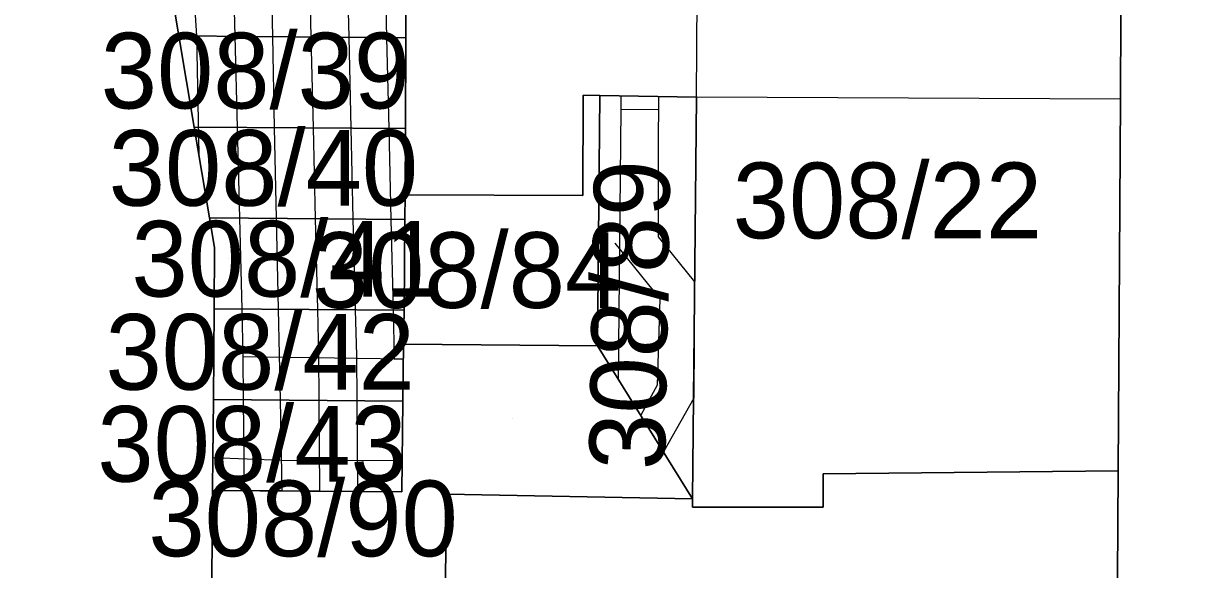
# Model space of a CAD drawing. Extents: x -263423 to -261326, y -1240067 to -1237864.
# Drawn here: x -263138.22 to -263106.91, y -1239151.4 to -1239136.99 of the extents above; entities that cross this region are included whole.
import ezdxf

# ---------------------------------------------------------------- set-up
doc = ezdxf.new("R2010")
doc.units = 0
for name, color, linetype in [('body_kn', 7, 'Continuous'), ('kladpar_druhypozemkov', 7, 'Continuous'), ('kladpar_hranice', 7, 'Continuous'), ('kladpar_parcelnecisla', 7, 'Continuous'), ('kladpar_plochy', 7, 'Continuous'), ('tarchy_linie', 7, 'Continuous'), ('zappar_hrandruhpozemk', 7, 'Continuous')]:
    doc.layers.add(name, color=color, linetype=linetype)

msp = doc.modelspace()

# ---------------------------------------------------------------- linework, layer by layer
at = {"layer": 'body_kn'}
for p, q in [((-263134.12, -1239137.31), (-263134.12, -1239137.31)), ((-263134.12, -1239137.31), (-263134.12, -1239137.31)), ((-263133.65, -1239137.31), (-263133.65, -1239137.31)), ((-263132.64, -1239137.32), (-263132.64, -1239137.32)), ((-263131.65, -1239137.33), (-263131.65, -1239137.33)), ((-263130.63, -1239137.34), (-263130.63, -1239137.34)), ((-263129.63, -1239137.35), (-263129.63, -1239137.35)), ((-263128.63, -1239137.36), (-263128.63, -1239137.36)), ((-263128.12, -1239137.36), (-263128.12, -1239137.36)), ((-263123.43, -1239138.88), (-263123.43, -1239138.88)), ((-263122.99, -1239138.89), (-263122.99, -1239138.89)), ((-263122.99, -1239138.89), (-263122.99, -1239138.89)), ((-263122.44, -1239138.9), (-263122.44, -1239138.9)), ((-263122.44, -1239138.9), (-263122.44, -1239138.9)), ((-263121.44, -1239138.91), (-263121.44, -1239138.91)), ((-263121.44, -1239138.91), (-263121.44, -1239138.91)), ((-263120.44, -1239138.93), (-263120.44, -1239138.93)), ((-263120.44, -1239138.93), (-263120.44, -1239138.93)), ((-263109.23, -1239138.98), (-263109.23, -1239138.98)), ((-263109.23, -1239138.98), (-263109.23, -1239138.98)), ((-263122.44, -1239139.25), (-263122.44, -1239139.25)), ((-263122.44, -1239139.25), (-263122.44, -1239139.25)), ((-263121.46, -1239139.26), (-263121.46, -1239139.26)), ((-263133.72, -1239139.72), (-263133.72, -1239139.72)), ((-263133.72, -1239139.72), (-263133.72, -1239139.72)), ((-263132.58, -1239139.73), (-263132.58, -1239139.73)), ((-263131.6, -1239139.74), (-263131.6, -1239139.74)), ((-263130.57, -1239139.74), (-263130.57, -1239139.74)), ((-263129.58, -1239139.75), (-263129.58, -1239139.75)), ((-263128.57, -1239139.76), (-263128.57, -1239139.76)), ((-263128.13, -1239139.76), (-263128.13, -1239139.76)), ((-263121.45, -1239140.26), (-263121.45, -1239140.26)), ((-263133.59, -1239140.45), (-263133.59, -1239140.45)), ((-263128.14, -1239141.51), (-263128.14, -1239141.51)), ((-263128.14, -1239141.51), (-263128.14, -1239141.51)), ((-263123.44, -1239141.53), (-263123.44, -1239141.53)), ((-263133.31, -1239142.12), (-263133.31, -1239142.12)), ((-263133.31, -1239142.12), (-263133.31, -1239142.12)), ((-263132.52, -1239142.13), (-263132.52, -1239142.13)), ((-263131.55, -1239142.13), (-263131.55, -1239142.13)), ((-263130.52, -1239142.14), (-263130.52, -1239142.14)), ((-263129.52, -1239142.15), (-263129.52, -1239142.15)), ((-263128.52, -1239142.16), (-263128.52, -1239142.16)), ((-263128.15, -1239142.16), (-263128.15, -1239142.16)), ((-263133.18, -1239142.9), (-263133.18, -1239142.9)), ((-263122.6, -1239142.79), (-263122.6, -1239142.79)), ((-263121.45, -1239142.62), (-263121.45, -1239142.62)), ((-263120.49, -1239143.81), (-263120.49, -1239143.81)), ((-263121.41, -1239144.26), (-263121.41, -1239144.26)), ((-263133.19, -1239144.52), (-263133.19, -1239144.52)), ((-263133.19, -1239144.52), (-263133.19, -1239144.52)), ((-263132.46, -1239144.53), (-263132.46, -1239144.53)), ((-263131.5, -1239144.53), (-263131.5, -1239144.53)), ((-263130.46, -1239144.54), (-263130.46, -1239144.54)), ((-263129.46, -1239144.55), (-263129.46, -1239144.55)), ((-263128.46, -1239144.56), (-263128.46, -1239144.56)), ((-263128.17, -1239144.56), (-263128.17, -1239144.56)), ((-263128.18, -1239145.46), (-263128.18, -1239145.46)), ((-263128.18, -1239145.46), (-263128.18, -1239145.46)), ((-263123.05, -1239145.5), (-263123.05, -1239145.5)), ((-263132.43, -1239145.78), (-263132.43, -1239145.78)), ((-263132.43, -1239145.78), (-263132.43, -1239145.78)), ((-263130.43, -1239145.76), (-263130.43, -1239145.76)), ((-263129.43, -1239145.76), (-263129.43, -1239145.76)), ((-263128.43, -1239145.84), (-263128.43, -1239145.84)), ((-263128.19, -1239145.84), (-263128.19, -1239145.84)), ((-263122.51, -1239146.37), (-263122.51, -1239146.37)), ((-263121.48, -1239146.54), (-263121.48, -1239146.54)), ((-263133.21, -1239146.92), (-263133.21, -1239146.92)), ((-263133.21, -1239146.92), (-263133.21, -1239146.92)), ((-263132.42, -1239146.93), (-263132.42, -1239146.93)), ((-263131.44, -1239146.93), (-263131.44, -1239146.93)), ((-263130.42, -1239146.94), (-263130.42, -1239146.94)), ((-263129.42, -1239146.95), (-263129.42, -1239146.95)), ((-263128.2, -1239146.96), (-263128.2, -1239146.96)), ((-263120.51, -1239146.88), (-263120.51, -1239146.88)), ((-263121.91, -1239147.33), (-263121.91, -1239147.33)), ((-263133.22, -1239148.45), (-263133.22, -1239148.45)), ((-263133.22, -1239148.45), (-263133.22, -1239148.45)), ((-263131.41, -1239148.52), (-263131.41, -1239148.52)), ((-263128.22, -1239148.53), (-263128.22, -1239148.53)), ((-263121.31, -1239148.3), (-263121.31, -1239148.3)), ((-263109.29, -1239148.8), (-263109.29, -1239148.8)), ((-263109.29, -1239148.8), (-263109.29, -1239148.8)), ((-263117.09, -1239148.88), (-263117.09, -1239148.88)), ((-263133.23, -1239149.24), (-263133.23, -1239149.24)), ((-263133.23, -1239149.32), (-263133.23, -1239149.32)), ((-263132.4, -1239149.33), (-263132.4, -1239149.33)), ((-263131.4, -1239149.33), (-263131.4, -1239149.33)), ((-263130.4, -1239149.34), (-263130.4, -1239149.34)), ((-263129.4, -1239149.35), (-263129.4, -1239149.35)), ((-263128.23, -1239149.36), (-263128.23, -1239149.36)), ((-263127.04, -1239149.42), (-263127.04, -1239149.42)), ((-263120.54, -1239149.54), (-263120.54, -1239149.54)), ((-263120.54, -1239149.76), (-263120.54, -1239149.76)), ((-263117.09, -1239149.76), (-263117.09, -1239149.76))]:
    msp.add_line(p, q, dxfattribs=at)
at = {"layer": 'kladpar_druhypozemkov'}
for p, q in [((-263133.46, -1239138.67), (-263133.46, -1239138.67)), ((-263121.67, -1239140.66), (-263121.67, -1239140.66)), ((-263114.25, -1239140.49), (-263114.25, -1239140.49)), ((-263133.06, -1239141.1), (-263133.06, -1239141.1)), ((-263132.8, -1239143.2), (-263132.8, -1239143.2)), ((-263125.56, -1239142.92), (-263125.56, -1239142.92)), ((-263132.7, -1239145.46), (-263132.7, -1239145.46)), ((-263125.29, -1239147.43), (-263125.29, -1239147.43)), ((-263132.74, -1239147.95), (-263132.74, -1239147.95))]:
    msp.add_line(p, q, dxfattribs=at)
at = {"layer": 'kladpar_hranice'}
for points in [[(-263109.94, -1239245.97), (-263109.67, -1239225.01), (-263109.65, -1239221.25), (-263109.56, -1239207.16), (-263109.54, -1239204.81), (-263109.49, -1239191.74), (-263109.45, -1239177.44), (-263109.44, -1239175.46), (-263109.41, -1239167.25), (-263109.38, -1239162.9), (-263109.29, -1239148.8), (-263109.23, -1239138.98), (-263109.22, -1239136.74), (-263109.18, -1239130.59), (-263109.17, -1239129.29), (-263109.11, -1239122.06), (-263109.09, -1239120.08), (-263108.99, -1239107.41), (-263108.91, -1239098.07), (-263106.26, -1239098.89)], [(-263137.77, -1239115.71), (-263137.35, -1239118.19), (-263136.76, -1239121.69), (-263136.35, -1239124.1), (-263135.95, -1239126.5), (-263135.54, -1239128.9), (-263135.34, -1239130.11), (-263134.93, -1239132.51), (-263134.53, -1239134.91), (-263134.12, -1239137.31), (-263133.72, -1239139.72), (-263133.31, -1239142.12), (-263133.18, -1239142.9), (-263133.19, -1239144.52), (-263133.21, -1239146.92), (-263133.23, -1239149.24), (-263133.23, -1239149.32), (-263133.25, -1239151.72)], [(-263109.17, -1239129.29), (-263109.18, -1239130.59), (-263109.22, -1239136.74), (-263109.23, -1239138.98), (-263109.29, -1239148.8), (-263117.09, -1239148.88), (-263117.09, -1239149.76), (-263120.54, -1239149.76), (-263120.54, -1239149.54), (-263120.44, -1239138.93), (-263122.99, -1239138.89), (-263123.43, -1239138.88), (-263123.44, -1239141.53), (-263128.14, -1239141.51), (-263128.13, -1239139.76), (-263128.12, -1239137.36), (-263128.12, -1239136.21), (-263122.97, -1239136.23), (-263120.42, -1239136.24), (-263120.36, -1239129.24), (-263109.17, -1239129.29)], [(-263134.53, -1239134.91), (-263128.11, -1239134.97), (-263128.12, -1239136.21), (-263128.12, -1239137.36), (-263134.12, -1239137.31), (-263134.53, -1239134.91)], [(-263134.12, -1239137.31), (-263128.12, -1239137.36), (-263128.13, -1239139.76), (-263133.72, -1239139.72), (-263134.12, -1239137.31)], [(-263128.14, -1239141.51), (-263123.44, -1239141.53), (-263123.43, -1239138.88), (-263122.99, -1239138.89), (-263123.05, -1239145.5), (-263128.18, -1239145.46), (-263128.17, -1239144.56), (-263128.15, -1239142.16), (-263128.14, -1239141.51)], [(-263122.99, -1239138.89), (-263120.44, -1239138.93), (-263120.54, -1239149.54), (-263123.05, -1239145.5), (-263122.99, -1239138.89)], [(-263133.72, -1239139.72), (-263128.13, -1239139.76), (-263128.14, -1239141.51), (-263128.15, -1239142.16), (-263133.31, -1239142.12), (-263133.72, -1239139.72)], [(-263133.31, -1239142.12), (-263128.15, -1239142.16), (-263128.17, -1239144.56), (-263133.19, -1239144.52), (-263133.18, -1239142.9), (-263133.31, -1239142.12)], [(-263133.19, -1239144.52), (-263128.17, -1239144.56), (-263128.18, -1239145.46), (-263128.2, -1239146.96), (-263133.21, -1239146.92), (-263133.19, -1239144.52)], [(-263128.18, -1239145.46), (-263123.05, -1239145.5), (-263120.54, -1239149.54), (-263127.04, -1239149.42), (-263127.26, -1239162.46), (-263120.71, -1239162.48), (-263123.21, -1239164.91), (-263128.4, -1239164.86), (-263128.37, -1239162.46), (-263128.34, -1239160.06), (-263128.31, -1239157.66), (-263128.29, -1239155.26), (-263128.25, -1239151.76), (-263133.25, -1239151.72), (-263133.23, -1239149.32), (-263128.23, -1239149.36), (-263128.2, -1239146.96), (-263128.18, -1239145.46)], [(-263133.21, -1239146.92), (-263128.2, -1239146.96), (-263128.23, -1239149.36), (-263133.23, -1239149.32), (-263133.23, -1239149.24), (-263133.21, -1239146.92)], [(-263109.29, -1239148.8), (-263109.38, -1239162.9), (-263117.25, -1239162.89), (-263117.25, -1239162.26), (-263120.71, -1239162.26), (-263120.71, -1239162.48), (-263127.26, -1239162.46), (-263127.04, -1239149.42), (-263120.54, -1239149.54), (-263120.54, -1239149.76), (-263117.09, -1239149.76), (-263117.09, -1239148.88), (-263109.29, -1239148.8)]]:
    msp.add_lwpolyline(points, dxfattribs=at)
at = {"layer": 'kladpar_plochy'}
for points in [[(-263109.94, -1239245.97), (-263109.67, -1239225.01), (-263109.65, -1239221.25), (-263109.56, -1239207.16), (-263109.54, -1239204.81), (-263109.49, -1239191.74), (-263109.45, -1239177.44), (-263109.44, -1239175.46), (-263109.41, -1239167.25), (-263109.38, -1239162.9), (-263109.29, -1239148.8), (-263109.23, -1239138.98), (-263109.22, -1239136.74), (-263109.18, -1239130.59), (-263109.17, -1239129.29), (-263109.11, -1239122.06), (-263109.09, -1239120.08), (-263108.99, -1239107.41), (-263108.91, -1239098.07), (-263106.26, -1239098.89)], [(-263139.08, -1239191.26), (-263138.73, -1239149.18), (-263138.68, -1239143.22), (-263143.22, -1239116.4), (-263141.86, -1239116.23), (-263138.85, -1239115.85), (-263137.77, -1239115.71), (-263137.35, -1239118.19), (-263136.76, -1239121.69), (-263136.35, -1239124.1), (-263135.95, -1239126.5), (-263135.54, -1239128.9), (-263135.34, -1239130.11), (-263134.93, -1239132.51), (-263134.53, -1239134.91), (-263134.12, -1239137.31), (-263133.72, -1239139.72), (-263133.31, -1239142.12), (-263133.18, -1239142.9), (-263133.19, -1239144.52), (-263133.21, -1239146.92), (-263133.23, -1239149.24), (-263133.23, -1239149.32), (-263133.25, -1239151.72)]]:
    msp.add_lwpolyline(points, dxfattribs=at)
for points in [[(-263109.17, -1239129.29), (-263109.18, -1239130.59), (-263109.22, -1239136.74), (-263109.23, -1239138.98), (-263109.29, -1239148.8), (-263117.09, -1239148.88), (-263117.09, -1239149.76), (-263120.54, -1239149.76), (-263120.54, -1239149.54), (-263120.44, -1239138.93), (-263122.99, -1239138.89), (-263123.43, -1239138.88), (-263123.44, -1239141.53), (-263128.14, -1239141.51), (-263128.13, -1239139.76), (-263128.12, -1239137.36), (-263128.12, -1239136.21), (-263122.97, -1239136.23), (-263120.42, -1239136.24), (-263120.36, -1239129.24)], [(-263134.53, -1239134.91), (-263128.11, -1239134.97), (-263128.12, -1239136.21), (-263128.12, -1239137.36), (-263134.12, -1239137.31)], [(-263134.12, -1239137.31), (-263128.12, -1239137.36), (-263128.13, -1239139.76), (-263133.72, -1239139.72)], [(-263128.14, -1239141.51), (-263123.44, -1239141.53), (-263123.43, -1239138.88), (-263122.99, -1239138.89), (-263123.05, -1239145.5), (-263128.18, -1239145.46), (-263128.17, -1239144.56), (-263128.15, -1239142.16)], [(-263122.99, -1239138.89), (-263120.44, -1239138.93), (-263120.54, -1239149.54), (-263123.05, -1239145.5)], [(-263133.72, -1239139.72), (-263128.13, -1239139.76), (-263128.14, -1239141.51), (-263128.15, -1239142.16), (-263133.31, -1239142.12)], [(-263133.31, -1239142.12), (-263128.15, -1239142.16), (-263128.17, -1239144.56), (-263133.19, -1239144.52), (-263133.18, -1239142.9)], [(-263133.19, -1239144.52), (-263128.17, -1239144.56), (-263128.18, -1239145.46), (-263128.2, -1239146.96), (-263133.21, -1239146.92)], [(-263128.18, -1239145.46), (-263123.05, -1239145.5), (-263120.54, -1239149.54), (-263127.04, -1239149.42), (-263127.26, -1239162.46), (-263120.71, -1239162.48), (-263123.21, -1239164.91), (-263128.4, -1239164.86), (-263128.37, -1239162.46), (-263128.34, -1239160.06), (-263128.31, -1239157.66), (-263128.29, -1239155.26), (-263128.25, -1239151.76), (-263133.25, -1239151.72), (-263133.23, -1239149.32), (-263128.23, -1239149.36), (-263128.2, -1239146.96)], [(-263133.21, -1239146.92), (-263128.2, -1239146.96), (-263128.23, -1239149.36), (-263133.23, -1239149.32), (-263133.23, -1239149.24)], [(-263109.29, -1239148.8), (-263109.38, -1239162.9), (-263117.25, -1239162.89), (-263117.25, -1239162.26), (-263120.71, -1239162.26), (-263120.71, -1239162.48), (-263127.26, -1239162.46), (-263127.04, -1239149.42), (-263120.54, -1239149.54), (-263120.54, -1239149.76), (-263117.09, -1239149.76), (-263117.09, -1239148.88)]]:
    msp.add_lwpolyline(points, close=True, dxfattribs=at)
at = {"layer": 'tarchy_linie'}
for p, q in [((-263122.44, -1239139.25), (-263121.46, -1239139.26)), ((-263132.43, -1239145.78), (-263128.19, -1239145.84))]:
    msp.add_line(p, q, dxfattribs=at)
for points in [[(-263137.74, -1239115.9), (-263136.09, -1239115.75), (-263134.9, -1239118.21), (-263133.2, -1239121.72), (-263132.02, -1239124.15), (-263129.84, -1239128.65), (-263129.83, -1239128.95), (-263129.8, -1239130.16), (-263129.75, -1239132.56), (-263129.7, -1239134.66), (-263129.69, -1239134.96), (-263129.63, -1239137.35), (-263129.58, -1239139.75), (-263129.52, -1239142.15), (-263129.46, -1239144.55), (-263129.43, -1239145.76), (-263129.42, -1239146.95), (-263129.4, -1239149.35)], [(-263136.25, -1239117.18), (-263135.78, -1239118.2), (-263134.15, -1239121.71), (-263133.03, -1239124.14), (-263131.92, -1239126.54), (-263130.84, -1239128.88), (-263130.84, -1239128.94), (-263130.81, -1239130.15), (-263130.75, -1239132.55), (-263130.73, -1239133.16), (-263130.69, -1239134.95), (-263130.63, -1239137.34), (-263130.57, -1239139.74), (-263130.52, -1239142.14), (-263130.46, -1239144.54), (-263130.43, -1239145.76), (-263130.42, -1239146.94), (-263130.4, -1239149.34)], [(-263136.57, -1239122.84), (-263135.59, -1239124.01), (-263135.54, -1239124.11), (-263134.32, -1239126.51), (-263133.1, -1239128.92), (-263132.84, -1239129.43), (-263132.82, -1239130.13), (-263132.76, -1239132.53), (-263132.7, -1239134.93), (-263132.64, -1239137.32), (-263132.58, -1239139.73), (-263132.52, -1239142.13), (-263132.46, -1239144.53), (-263132.43, -1239145.78), (-263132.42, -1239146.93), (-263132.4, -1239149.33)], [(-263131.83, -1239129.12), (-263131.81, -1239130.14), (-263131.76, -1239132.54), (-263131.7, -1239134.94), (-263131.65, -1239137.33), (-263131.6, -1239139.74), (-263131.55, -1239142.13), (-263131.5, -1239144.53), (-263131.44, -1239146.93), (-263131.4, -1239149.33)], [(-263128.67, -1239135.7), (-263128.63, -1239137.36), (-263128.57, -1239139.76), (-263128.52, -1239142.16), (-263128.46, -1239144.56), (-263128.43, -1239145.84), (-263128.19, -1239145.84), (-263128.22, -1239148.53), (-263128.23, -1239149.36), (-263129.4, -1239149.35), (-263130.4, -1239149.34), (-263131.4, -1239149.33), (-263132.4, -1239149.33), (-263133.23, -1239149.32), (-263133.22, -1239148.45), (-263133.21, -1239146.92), (-263133.19, -1239144.52), (-263133.18, -1239142.9), (-263133.31, -1239142.12), (-263133.59, -1239140.45), (-263133.65, -1239137.31), (-263133.72, -1239136.21)], [(-263121.44, -1239138.91), (-263121.45, -1239140.26), (-263121.45, -1239142.62), (-263120.49, -1239143.81), (-263120.51, -1239146.88), (-263121.31, -1239148.3), (-263121.91, -1239147.33), (-263122.51, -1239146.37), (-263123.05, -1239145.5), (-263122.99, -1239138.89), (-263122.44, -1239138.9), (-263121.44, -1239138.91)], [(-263122.44, -1239138.9), (-263122.44, -1239139.25), (-263122.51, -1239146.37)], [(-263122.6, -1239142.79), (-263121.41, -1239144.26), (-263121.48, -1239146.54), (-263121.91, -1239147.33)], [(-263133.22, -1239148.45), (-263131.41, -1239148.52), (-263128.22, -1239148.53)]]:
    msp.add_lwpolyline(points, dxfattribs=at)
at = {"layer": 'zappar_hrandruhpozemk'}
for p, q in [((-263120.44, -1239138.93), (-263120.42, -1239136.24)), ((-263109.23, -1239138.98), (-263120.44, -1239138.93))]:
    msp.add_line(p, q, dxfattribs=at)

# ---------------------------------------------------------------- texts
at = {"layer": 'kladpar_parcelnecisla'}
for s, p in [('308/39', (-263136.188, -1239139.23)), ('308/40', (-263135.977, -1239141.8)), ('308/22', (-263119.479, -1239142.66)), ('308/41', (-263135.376, -1239144.2)), ('308/84', (-263130.607, -1239144.5)), ('308/42', (-263136.062, -1239146.66)), ('308/43', (-263136.278, -1239149.09))]:
    msp.add_text(s, height=2, dxfattribs=at).set_placement(p)
for s, rotation, p in [('308/89', 89, (-263121.278, -1239148.793)), ('308/90', 360, (-263134.927, -1239151.06))]:
    msp.add_text(s, height=2, rotation=rotation, dxfattribs=at).set_placement(p)

doc.saveas('drawing.dxf')
